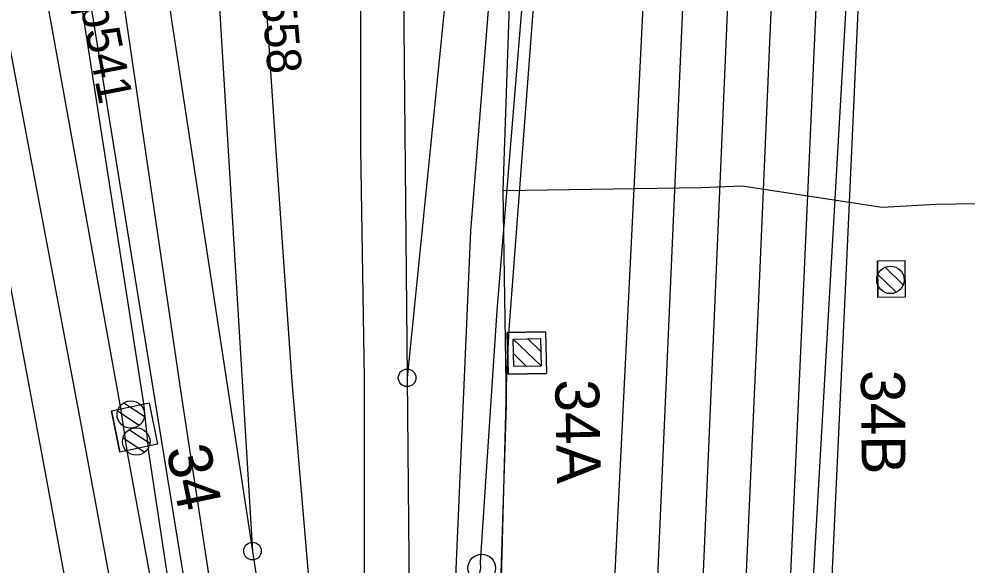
# Model space of a CAD drawing. Extents: x -545736 to -544888, y -1122892 to -1119128.
# Drawn here: x -545149.33 to -545114.79, y -1122049.98 to -1122030.09 of the extents above; entities that cross this region are included whole.
import ezdxf

# ---------------------------------------------------------------- set-up
doc = ezdxf.new("R2010")
doc.units = 0
for name, color, linetype in [('osvětlené plochy-hodnota-obrys', 7, 'Continuous'), ('Vrstva 1 - Koleje', 7, 'Continuous'), ('Vrstva 11 - Trakce', 7, 'Continuous'), ('Vrstva 12 - Trakce zaklady', 7, 'Continuous'), ('Vrstva 2 - Vyhybky', 7, 'Continuous'), ('Vrstva 28 - zabzar', 7, 'Continuous'), ('Vrstva 35', 7, 'Continuous'), ('Vrstva 4 - Teren - stezky - prechody - plochy', 7, 'Continuous'), ('Vrstva 43', 7, 'Continuous'), ('Vrstva 44', 7, 'Continuous')]:
    doc.layers.add(name, color=color, linetype=linetype)

msp = doc.modelspace()

# ---------------------------------------------------------------- linework, layer by layer
at = {"layer": 'osvětlené plochy-hodnota-obrys'}
msp.add_lwpolyline([(-545141.742, -1122267.38), (-545105.592, -1122261.055), (-545104.447, -1122260.603), (-545110.322, -1122216.729), (-545115.194, -1122188.84), (-545124.338, -1122134.271), (-545128.334, -1122064.958), (-545124.139, -1121980.114), (-545129.58, -1121934.549), (-545137.864, -1121889.42)], dxfattribs=at)
at = {"layer": 'Vrstva 1 - Koleje'}
for points in [[(-545161.662, -1121928.056), (-545159.744, -1121937.904), (-545157.825, -1121947.729), (-545156.674, -1121953.63), (-545154.785, -1121963.328), (-545152.88, -1121973.098), (-545151.044, -1121983.182), (-545149.436, -1121992.894), (-545149.139, -1121994.831), (-545148.849, -1121996.72), (-545147.636, -1122004.722), (-545146.16, -1122014.426), (-545145.692, -1122017.507), (-545145.04, -1122021.804), (-545143.834, -1122029.732), (-545140.823, -1122049.47), (-545138.891, -1122062.139), (-545138.77, -1122062.93)], [(-545156.492, -1121929.766), (-545154.597, -1121939.5), (-545152.98, -1121947.786), (-545151.506, -1121955.339), (-545149.849, -1121963.83), (-545148.474, -1121971.119), (-545147.387, -1121977.432), (-545147.132, -1121979.027), (-545146.813, -1121981.027), (-545145.63, -1121989.169), (-545144.608, -1121997.318), (-545143.884, -1122004.032), (-545143.167, -1122012), (-545142.729, -1122017.98), (-545142.509, -1122021.543), (-545142.219, -1122026.383), (-545142.033, -1122029.495), (-545140.823, -1122049.47), (-545138.891, -1122062.139), (-545138.77, -1122062.93)], [(-545169.885, -1121935.194), (-545167.829, -1121945.733), (-545165.916, -1121955.547), (-545164.023, -1121965.263), (-545162.116, -1121975.05), (-545160.205, -1121984.882), (-545158.3, -1121994.663), (-545156.394, -1122004.452), (-545154.492, -1122014.326), (-545152.816, -1122023.106), (-545151.624, -1122029.361), (-545150.011, -1122037.912), (-545148.44, -1122046.297), (-545146.992, -1122054.103), (-545145.125, -1122064.246), (-545144.947, -1122065.222), (-545144.042, -1122070.186), (-545142.439, -1122079.045)], [(-545126.105, -1121936.121), (-545124.989, -1121942.721), (-545123.777, -1121951.017), (-545122.797, -1121959.071), (-545122.52, -1121961.826), (-545122.146, -1121965.538), (-545121.796, -1121969.686), (-545121.227, -1121978.385), (-545120.892, -1121986.982), (-545120.771, -1121995.363), (-545120.842, -1122002.901), (-545120.963, -1122007.395), (-545121.273, -1122014.923), (-545121.363, -1122016.964), (-545121.593, -1122022.181), (-545121.982, -1122030.948), (-545122.393, -1122040.282), (-545122.646, -1122045.924), (-545122.996, -1122053.751), (-545123.445, -1122063.966), (-545123.814, -1122072.276), (-545124.174, -1122080.378)], [(-545132.79, -1122019.463), (-545133.203, -1122023.514), (-545133.334, -1122024.813), (-545133.519, -1122026.639), (-545135.191, -1122043.162), (-545135.039, -1122058.979), (-545135.031, -1122059.769)], [(-545135.406, -1122020.747), (-545135.35, -1122026.563), (-545135.191, -1122043.162), (-545135.039, -1122058.979), (-545135.031, -1122059.769)]]:
    msp.add_lwpolyline(points, dxfattribs=at)
at = {"layer": 'Vrstva 11 - Trakce'}
for p, q in [((-545117.769, -1122039.136), (-545117.117, -1122039.776)), ((-545118.037, -1122039.398), (-545117.376, -1122040.047)), ((-545131.324, -1122041.753), (-545130.309, -1122042.73)), ((-545130.795, -1122041.742), (-545130.319, -1122042.2)), ((-545131.317, -1122042.28), (-545130.835, -1122042.743)), ((-545145.511, -1122044.067), (-545144.765, -1122044.557)), ((-545145.739, -1122044.366), (-545144.947, -1122044.887)), ((-545145.311, -1122045.049), (-545144.563, -1122045.54)), ((-545145.538, -1122045.349), (-545144.747, -1122045.868))]:
    msp.add_line(p, q, dxfattribs=at)
msp.add_lwpolyline([(-545130.328, -1122041.734), (-545130.309, -1122042.733), (-545131.308, -1122042.752), (-545131.327, -1122041.753)], close=True, dxfattribs=at)
for centre in [(-545117.581, -1122039.595), (-545145.26, -1122044.498), (-545145.058, -1122045.478)]:
    msp.add_circle(centre, 0.5, dxfattribs=at)
at = {"layer": 'Vrstva 12 - Trakce zaklady'}
for p, q in [((-545118.058, -1122038.9), (-545117.058, -1122038.891)), ((-545117.046, -1122040.225), (-545118.046, -1122040.234)), ((-545131.543, -1122041.508), (-545131.514, -1122043.031)), ((-545130.143, -1122041.481), (-545130.114, -1122043.004)), ((-545145.965, -1122044.357), (-545144.594, -1122044.073)), ((-545144.282, -1122045.579), (-545145.653, -1122045.863))]:
    msp.add_line(p, q, dxfattribs=at)
for points in [[(-545118.046, -1122040.234), (-545118.058, -1122038.9), (-545117.058, -1122038.891), (-545117.046, -1122040.225), (-545118.046, -1122040.234)], [(-545118.058, -1122038.9), (-545118.058, -1122038.9), (-545118.046, -1122040.234), (-545118.046, -1122040.234)], [(-545117.058, -1122038.891), (-545117.058, -1122038.891), (-545117.046, -1122040.225), (-545117.046, -1122040.225)], [(-545131.514, -1122043.031), (-545131.543, -1122041.508), (-545130.143, -1122041.481), (-545130.114, -1122043.004), (-545131.514, -1122043.031)], [(-545130.143, -1122041.481), (-545130.143, -1122041.481), (-545131.543, -1122041.508), (-545131.543, -1122041.508)], [(-545131.514, -1122043.031), (-545131.514, -1122043.031), (-545130.114, -1122043.004), (-545130.114, -1122043.004)], [(-545144.594, -1122044.073), (-545144.282, -1122045.579), (-545145.653, -1122045.863), (-545145.965, -1122044.357), (-545144.594, -1122044.073)], [(-545144.594, -1122044.073), (-545144.594, -1122044.073), (-545144.282, -1122045.579), (-545144.282, -1122045.579)], [(-545145.965, -1122044.357), (-545145.965, -1122044.357), (-545145.653, -1122045.863), (-545145.653, -1122045.863)]]:
    msp.add_lwpolyline(points, dxfattribs=at)
at = {"layer": 'Vrstva 2 - Vyhybky'}
for points in [[(-545135.35, -1122026.563), (-545135.191, -1122043.162), (-545135.039, -1122058.979), (-545135.031, -1122059.769)], [(-545133.519, -1122026.639), (-545135.191, -1122043.162)], [(-545142.033, -1122029.495), (-545140.823, -1122049.47)], [(-545143.834, -1122029.732), (-545140.823, -1122049.47), (-545138.891, -1122062.139), (-545138.77, -1122062.93)]]:
    msp.add_lwpolyline(points, dxfattribs=at)
for centre in [(-545135.191, -1122043.162), (-545140.823, -1122049.47)]:
    msp.add_circle(centre, 0.32, dxfattribs=at)
at = {"layer": 'Vrstva 28 - zabzar'}
for points in [[(-545127.01, -1122123.01), (-545128.45, -1122112.3), (-545129.91, -1122102.44), (-545130.12, -1122100.23), (-545130.02, -1122098.77), (-545130.24, -1122093.73), (-545130.74, -1122089.35), (-545131, -1122087.03), (-545131.17, -1122083.74), (-545131.66, -1122076.12), (-545131.95, -1122065.09), (-545132.08, -1122064.03), (-545132.04, -1122061.55), (-545131.96, -1122058.03), (-545131.79, -1122051.05), (-545131.57, -1122044.14), (-545131.692, -1122036.343), (-545131.3, -1122024.96), (-545130.86, -1122020.8)], [(-545131.692, -1122036.343), (-545124.473, -1122036.231), (-545122.98, -1122036.166), (-545117.88, -1122036.94), (-545115.93, -1122036.84), (-545114.43, -1122036.81), (-545111.59, -1122036.74), (-545110.476, -1122036.858), (-545109.83, -1122036.71), (-545109.83, -1122036.17), (-545109.87, -1122035.32), (-545109.06, -1122035.39), (-545106.24, -1122035.31), (-545104.87, -1122035.26)]]:
    msp.add_lwpolyline(points, dxfattribs=at)
at = {"layer": 'Vrstva 35'}
for points in [[(-545131.692, -1122036.343), (-545124.473, -1122036.231), (-545122.98, -1122036.166), (-545117.88, -1122036.94)], [(-545115.93, -1122036.84), (-545114.43, -1122036.81), (-545111.59, -1122036.74), (-545110.476, -1122036.858)]]:
    msp.add_lwpolyline(points, dxfattribs=at)
at = {"layer": 'Vrstva 4 - Teren - stezky - prechody - plochy'}
for points in [[(-545130.927, -1121899.07), (-545130.648, -1121900.157), (-545131.454, -1121900.275), (-545126.343, -1121926.432), (-545123.993, -1121939.181), (-545122.36, -1121950.022), (-545121.15, -1121959.983), (-545120.161, -1121970.783), (-545119.318, -1121985.414), (-545119.166, -1121996.341), (-545119.647, -1122014.958), (-545120.73, -1122039.222), (-545122.244, -1122072.998), (-545123.427, -1122099.522)], [(-545130.927, -1121899.07), (-545129.932, -1121899.132), (-545124.65, -1121926.386), (-545122.28, -1121939.006), (-545120.69, -1121949.814), (-545119.511, -1121959.901), (-545118.523, -1121970.907), (-545117.746, -1121985.091), (-545117.62, -1121996.864), (-545117.689, -1122000.041), (-545117.66, -1122001.473), (-545118.101, -1122015.003), (-545119.169, -1122038.652), (-545120.773, -1122073.084), (-545121.846, -1122098.278)], [(-545126.473, -1121948.923), (-545126.334, -1121961.598), (-545126.775, -1121973.403), (-545128.646, -1121994.547), (-545129.488, -1122002.476), (-545132.005, -1122026.865), (-545132.877, -1122037.815), (-545133.414, -1122050.13), (-545133.441, -1122062.766), (-545133.197, -1122070.382), (-545132.437, -1122082.452), (-545132.119, -1122088.474), (-545131.133, -1122099.699), (-545129.153, -1122115.135), (-545127.499, -1122127.653)], [(-545126.473, -1121948.923), (-545125.498, -1121948.878), (-545124.184, -1121961.269), (-545123.043, -1121974.047), (-545122.441, -1121988.694), (-545122.5, -1122005.806), (-545125.338, -1122072.019), (-545126.673, -1122101.485), (-545126.806, -1122108.75), (-545126.872, -1122116.941), (-545126.568, -1122127.516), (-545127.499, -1122127.653)], [(-545124.588, -1121975.896), (-545125.381, -1121975.973), (-545127.1, -1121994.605), (-545127.824, -1122001.843), (-545127.936, -1122003.505), (-545130.359, -1122026.44), (-545131.479, -1122041.398), (-545131.574, -1122043.071), (-545131.763, -1122050.486), (-545131.671, -1122062.186), (-545131.587, -1122069.508), (-545131.465, -1122071.195), (-545130.904, -1122081.855), (-545130.59, -1122087.603), (-545130.381, -1122089.386), (-545129.466, -1122100.008), (-545129.347, -1122101.621), (-545128.799, -1122106.042)], [(-545124.588, -1121975.896), (-545123.969, -1121989.016), (-545124.103, -1122005.669), (-545127.033, -1122072.216), (-545128.137, -1122100.001), (-545128.245, -1122101.528), (-545128.406, -1122106.062), (-545128.799, -1122106.042)], [(-545136.892, -1122020.512), (-545137.923, -1122020.69), (-545137.783, -1122023.203), (-545140.748, -1122023.215), (-545139.972, -1122034.909), (-545139.394, -1122043.292), (-545138.553, -1122053.145), (-545137.365, -1122062.143)], [(-545136.892, -1122020.512), (-545136.891, -1122034.823), (-545136.757, -1122043.186), (-545136.751, -1122055.228), (-545136.419, -1122062.026), (-545137.365, -1122062.143)], [(-545133.405, -1122116.375), (-545134.411, -1122116.469), (-545137.844, -1122096.227), (-545141.752, -1122073.558), (-545147.149, -1122044.385), (-545150.888, -1122024.642), (-545146.335, -1122023.86)], [(-545133.405, -1122116.375), (-545134.922, -1122101.254), (-545135.901, -1122093.602), (-545138.886, -1122073.467), (-545143.407, -1122043.778), (-545146.335, -1122023.86)], [(-545142.21, -1122063.101), (-545145.389, -1122045.816), (-545145.616, -1122044.266), (-545148.988, -1122025.643), (-545147.714, -1122025.315)], [(-545142.21, -1122063.101), (-545141.997, -1122063.044), (-545144.596, -1122045.862), (-545144.784, -1122044.107), (-545147.714, -1122025.315)]]:
    msp.add_lwpolyline(points, dxfattribs=at)
at = {"layer": 'Vrstva 43'}
msp.add_circle((-545132.473, -1122050.088), 0.5, dxfattribs=at)
at = {"layer": 'Vrstva 44'}
for points in [[(-545121.958, -1122140.931), (-545122.648, -1122100.584), (-545120.974, -1122060.822), (-545118.759, -1122022.005), (-545118.816, -1122021.663)], [(-545131.987, -1122077.131), (-545132.051, -1122076.804), (-545132.484, -1122063.78), (-545132.57, -1122050.373), (-545132.502, -1122050.093), (-545132.518, -1122049.88), (-545131.91, -1122040.71), (-545130.586, -1122024.589), (-545130.659, -1122024.257)], [(-545135.113, -1122107.162), (-545140.717, -1122066.523), (-545146.986, -1122027.871), (-545147.057, -1122027.496)]]:
    msp.add_lwpolyline(points, dxfattribs=at)

# ---------------------------------------------------------------- texts
at = {"layer": 'Vrstva 11 - Trakce'}
for s, rotation, p in [('34B', 270.5154, (-545118.659, -1122042.878)), ('34A', 271.0909, (-545129.799, -1122043.224)), ('34', 281.7045, (-545143.977, -1122045.764))]:
    msp.add_text(s, height=1.6, rotation=rotation, dxfattribs=at).set_placement(p)
at = {"layer": 'Vrstva 43'}
for s, rotation, p in [('Šp558', 274.7624, (-545140.66, -1122027.311)), ('Šp541', 281.0323, (-545147.317, -1122028.503))]:
    msp.add_text(s, height=1.25, rotation=rotation, dxfattribs=at).set_placement(p)

doc.saveas('drawing.dxf')
